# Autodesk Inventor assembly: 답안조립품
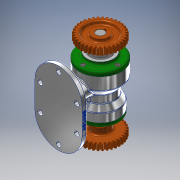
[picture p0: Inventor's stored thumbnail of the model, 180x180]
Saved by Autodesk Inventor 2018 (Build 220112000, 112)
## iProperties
Created: 2020-01
Part Number: 답안조립품
Document SubType Name: Assembly
Designer: Administrator
Author: Administrator
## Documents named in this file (13)
- C:\Users\Administrator\Desktop\700104V1041\답안조립품.iam
- C:\Users\Administrator\Desktop\700104V1041\본체.ipt
- C:\Users\Administrator\Desktop\700104V1041\축.ipt
- C:\Users\Administrator\Desktop\700104V1041\스퍼기어.ipt
- C:\Users\Administrator\Desktop\700104V1041\멈춤나사 M3.ipt
- C:\Users\Administrator\Desktop\700104V1041\Ű 5 x 5 x 18.ipt
- C:\Users\Administrator\Desktop\700104V1041\베어링 6205.ipt
- C:\Users\Administrator\Desktop\700104V1041\앞커버.ipt
- C:\Users\Administrator\Desktop\700104V1041\베어링 6203.ipt
- C:\Users\Administrator\Desktop\700104V1041\뒤커버.ipt
- C:\Users\Administrator\Desktop\700104V1041\볼트 M4.ipt
- C:\Users\Administrator\Desktop\700104V1041\오일 실 25 38 8.ipt
- C:\Users\Administrator\Desktop\700104V1041\오일 실 17 30 8.ipt
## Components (2 placed, 1 different names)
1. Ű 5 x 5 x 18:1
2. Ű 5 x 5 x 18:2 — 각도:1
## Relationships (1: Angle 1)
- 각도:1 [Angle]: Ű 5 x 5 x 18:2
